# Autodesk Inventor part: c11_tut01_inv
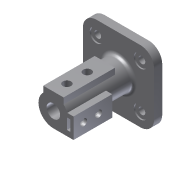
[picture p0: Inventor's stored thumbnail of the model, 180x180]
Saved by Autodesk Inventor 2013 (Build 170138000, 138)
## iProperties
Created: 2010-03
Part Number: c11_tut01_inv
Document SubType Name: Modeling
Designer: CADSoft
Density: 1 g/cm^3
Material: Generic
Author: CADSoft
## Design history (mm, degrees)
sketch "Sketch1"
  geometry: 1 further point
sketch "Sketch2"
  geometry: L1 (32.5, 52.5)-(-32.5, 52.5); L2 (-52.5, 32.5)-(-52.5, -32.5); L3 (-32.5, -52.5)-(32.5, -52.5); L4 (52.5, -32.5)-(52.5, 32.5); A1 r 20 centre (32.5, 32.5) between (52.5, 32.5) and (32.5, 52.5); A2 r 20 centre (-32.5, 32.5) between (-32.5, 52.5) and (-52.5, 32.5); A3 r 20 centre (-32.5, -32.5) between (-52.5, -32.5) and (-32.5, -52.5); A4 r 20 centre (32.5, -32.5) between (32.5, -52.5) and (52.5, -32.5); 4 further points
  constraints: 8 end point, 8 point on circle, 8 tangent, 6 point on line, 4 centre point, 3 equal radius, 3 perpendicular, 1 other
  dimensions: "d3" = 105 distance of point (52.5, 52.5) point (-52.5, 52.5); "d4" = 105 distance of point (52.5, -52.5) point (52.5, 52.5); "d6" = 52.5 distance from line of L1 point (0, 0); "d7" = 52.5 distance from line of L4 point (0, 0); "d8" = 20 radius of A1
extrude "Extrusion1" new body sketch "Sketch2" distance "d9" = 12; taper "d10" = 0 deg
hole "Hole1" diameter "d13" = 10; stored, may be unused: countersink angle "d17" = 90 deg, drill point angle "d19" = 118 deg; dims "d11" = 10, "d12" = 10, "d14" = 6, "d15" = 20, "d16" = 2, "d18" = 8
hole "Hole2" diameter "d22" = 10; stored, may be unused: countersink angle "d26" = 90 deg, drill point angle "d28" = 118 deg; dims "d20" = 10, "d21" = 10, "d23" = 6, "d24" = 20, "d25" = 2, "d27" = 8
hole "Hole3" diameter "d31" = 10; stored, may be unused: countersink angle "d35" = 90 deg, drill point angle "d37" = 118 deg; dims "d29" = 10, "d30" = 10, "d32" = 6, "d33" = 20, "d34" = 2, "d36" = 8
hole "Hole4" diameter "d40" = 10; stored, may be unused: countersink angle "d44" = 90 deg, drill point angle "d46" = 118 deg; dims "d38" = 10, "d39" = 10, "d41" = 6, "d42" = 20, "d43" = 2, "d45" = 8
sketch "Sketch3"
  geometry: C1 r 22 at (0, 0); 1 further point
  constraints: 1 centre point, 1 coincident
  dimensions: "d47" = 44 diameter of C1
extrude "Extrusion2" join sketch "Sketch3" distance "d48" = 96; taper "d49" = 0 deg
sketch "Sketch4"
  geometry: L1 (-15, 25)-(15, 25); L2 (15, 25)-(15, 16.093); L3 (-14.745, 16.328)-(-15, 16.093); L4 (-15, 16.093)-(-15, 25); A1 r 22 centre (0, 0) between (15, 16.093) and (-15, 16.093); 1 further point
  constraints: 8 end point, 4 point on circle, 2 vertical, 1 centre point, 1 coincident
  dimensions: "d50" = 30 distance of L1.start L1.end; "d52" = 15 distance from line of point (0, 0) L4; "d53" = 25 distance from line of point (0, 0) L1
extrude "Extrusion3" join sketch "Sketch4" distance "d54" = 76; taper "d55" = 0 deg
sketch "Sketch5"
  geometry: L1 (0, -22)-(29.709, -22); L2 (29.709, -22)-(29.709, 8); L3 (29.709, 8)-(20.494, 8); A1 r 22 centre (0, 0) between (0, -22) and (20.494, 8); 1 further point
  constraints: 6 end point, 2 point on circle, 1 centre point, 1 coincident
  dimensions: "d61" = 30 distance of L1.end L2.end
extrude "Extrusion4" join sketch "Sketch5" distance "d62" = 57; taper "d63" = 0 deg
sketch "Sketch6"
  geometry: L1 (20, 2)-(25, 2); L2 (25, 2)-(25, -14); L3 (25, -14)-(20, -14); L4 (20, -14)-(20, 2); A1 r 22 centre (0, 0) between (20.494, 8) and (15, 16.093) reference
  constraints: 8 end point
  dimensions: "d64" = 2 distance from line of A1.centre L1; "d66" = 25 distance from line of L2 A1.centre; "d67" = 5 distance of L2.end L3.end; "d68" = 16 distance of L1.end L2.end
extrude "Extrusion5" cut sketch "Sketch6" distance "d69" = 50; taper "d70" = 0 deg
hole "Hole5" diameter "d73" = 20; stored, may be unused: countersink angle "d77" = 90 deg, drill point angle "d79" = 0 deg; dims "d71" = 10, "d72" = 10, "d74" = 6, "d75" = 20, "d76" = 2, "d78" = 96
hole "Hole6" diameter "d82" = 12; stored, may be unused: countersink angle "d86" = 90 deg, drill point angle "d88" = 118 deg; dims "d80" = 20, "d81" = 15, "d83" = 6, "d84" = 20, "d85" = 2, "d87" = 96
hole "Hole7" diameter "d91" = 12; stored, may be unused: countersink angle "d95" = 90 deg, drill point angle "d97" = 118 deg; dims "d89" = 15, "d90" = 50, "d92" = 6, "d93" = 20, "d94" = 2, "d96" = 96
hole "Hole8" diameter "d100" = 10; stored, may be unused: countersink angle "d104" = 90 deg, drill point angle "d106" = 118 deg; dims "d98" = 15, "d99" = 15, "d101" = 6, "d102" = 20, "d103" = 2, "d105" = 96
hole "Hole9" diameter "d109" = 10; stored, may be unused: countersink angle "d113" = 90 deg, drill point angle "d115" = 118 deg; dims "d107" = 15, "d108" = 37, "d110" = 6, "d111" = 20, "d112" = 2, "d114" = 96
fillet "Fillet1" dims "d116" = 5
body "Solid1"
